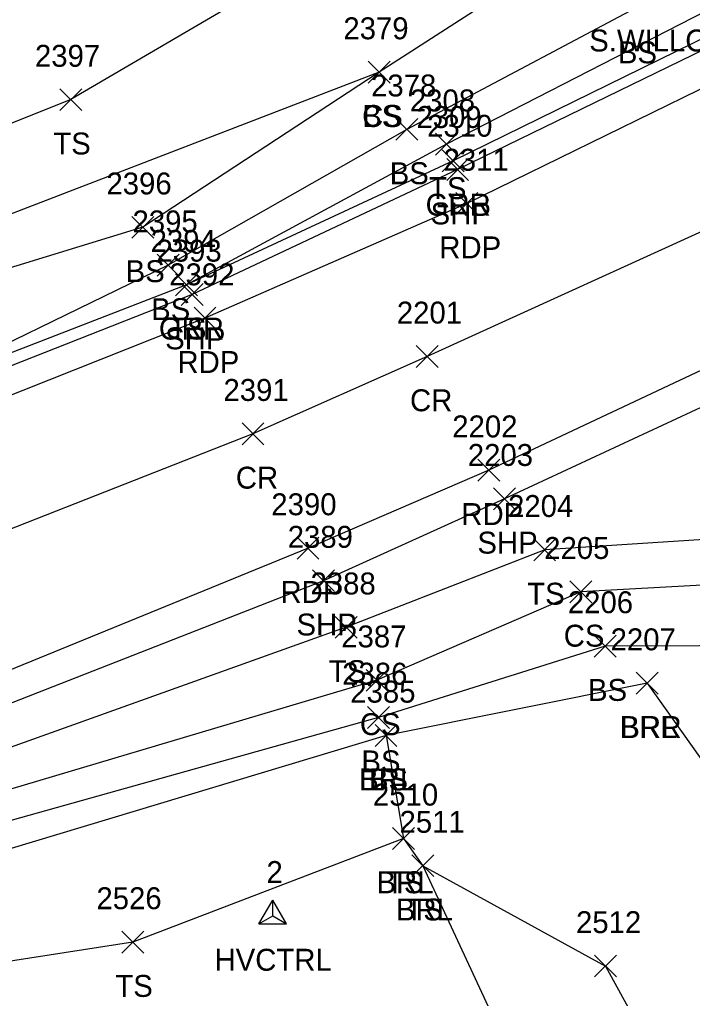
# Model space of a CAD drawing. Extents: x 1520648 to 1523413, y 732854 to 735518.
# Drawn here: x 1521920.9 to 1521982.3, y 733686.9 to 733776.2 of the extents above; entities that cross this region are included whole.
import ezdxf

# ---------------------------------------------------------------- set-up
doc = ezdxf.new("R2010")
doc.units = 0
for name, color, linetype in [('C_A', 7, 'Continuous'), ('C_I', 7, 'Continuous'), ('CPSM', 7, 'Continuous'), ('L_A', 7, 'Continuous'), ('L_C', 7, 'Continuous'), ('L_I', 7, 'Continuous'), ('L_TIC', 7, 'Continuous'), ('LABL', 7, 'Continuous'), ('LELB', 7, 'Continuous'), ('P_A', 7, 'Continuous'), ('P_I', 7, 'Continuous'), ('P_TIC', 7, 'Continuous'), ('PET', 7, 'Continuous'), ('PRC', 7, 'Continuous'), ('PSP', 7, 'Continuous'), ('R_A', 7, 'Continuous'), ('R_I', 7, 'Continuous'), ('R_TIC', 7, 'Continuous'), ('RGR', 7, 'Continuous')]:
    doc.layers.add(name, color=color, linetype=linetype)

msp = doc.modelspace()

# ---------------------------------------------------------------- linework, layer by layer
at = {"layer": 'CPSM'}
for p, q in [((1521942.773, 733693.671), (1521944.023, 733695.836)), ((1521942.773, 733693.671), (1521944.023, 733695.836)), ((1521942.773, 733693.671), (1521944.023, 733695.836)), ((1521942.773, 733693.671), (1521944.023, 733695.836)), ((1521942.773, 733693.671), (1521944.023, 733695.836)), ((1521942.773, 733693.671), (1521944.023, 733695.836)), ((1521942.773, 733693.671), (1521944.023, 733695.836)), ((1521942.773, 733693.671), (1521944.023, 733695.836)), ((1521945.273, 733693.671), (1521944.023, 733695.836)), ((1521944.023, 733694.392), (1521944.023, 733695.836)), ((1521945.273, 733693.671), (1521944.023, 733695.836)), ((1521944.023, 733694.392), (1521944.023, 733695.836)), ((1521945.273, 733693.671), (1521944.023, 733695.836)), ((1521944.023, 733694.392), (1521944.023, 733695.836)), ((1521945.273, 733693.671), (1521944.023, 733695.836)), ((1521944.023, 733694.392), (1521944.023, 733695.836)), ((1521945.273, 733693.671), (1521944.023, 733695.836)), ((1521944.023, 733694.392), (1521944.023, 733695.836)), ((1521945.273, 733693.671), (1521944.023, 733695.836)), ((1521944.023, 733694.392), (1521944.023, 733695.836)), ((1521945.273, 733693.671), (1521944.023, 733695.836)), ((1521944.023, 733694.392), (1521944.023, 733695.836)), ((1521945.273, 733693.671), (1521944.023, 733695.836)), ((1521944.023, 733694.392), (1521944.023, 733695.836)), ((1521942.773, 733693.671), (1521944.023, 733694.392)), ((1521942.773, 733693.671), (1521944.023, 733694.392)), ((1521942.773, 733693.671), (1521944.023, 733694.392)), ((1521942.773, 733693.671), (1521944.023, 733694.392)), ((1521942.773, 733693.671), (1521944.023, 733694.392)), ((1521942.773, 733693.671), (1521944.023, 733694.392)), ((1521942.773, 733693.671), (1521944.023, 733694.392)), ((1521942.773, 733693.671), (1521944.023, 733694.392)), ((1521944.023, 733694.392), (1521944.023, 733694.392)), ((1521944.023, 733694.392), (1521945.273, 733693.671)), ((1521944.023, 733694.392), (1521944.023, 733694.392)), ((1521944.023, 733694.392), (1521945.273, 733693.671)), ((1521944.023, 733694.392), (1521944.023, 733694.392)), ((1521944.023, 733694.392), (1521945.273, 733693.671)), ((1521944.023, 733694.392), (1521944.023, 733694.392)), ((1521944.023, 733694.392), (1521945.273, 733693.671)), ((1521944.023, 733694.392), (1521944.023, 733694.392)), ((1521944.023, 733694.392), (1521945.273, 733693.671)), ((1521944.023, 733694.392), (1521944.023, 733694.392)), ((1521944.023, 733694.392), (1521945.273, 733693.671)), ((1521944.023, 733694.392), (1521944.023, 733694.392)), ((1521944.023, 733694.392), (1521945.273, 733693.671)), ((1521944.023, 733694.392), (1521944.023, 733694.392)), ((1521944.023, 733694.392), (1521945.273, 733693.671)), ((1521942.773, 733693.671), (1521945.273, 733693.671)), ((1521942.773, 733693.671), (1521945.273, 733693.671)), ((1521942.773, 733693.671), (1521945.273, 733693.671)), ((1521942.773, 733693.671), (1521945.273, 733693.671)), ((1521942.773, 733693.671), (1521945.273, 733693.671)), ((1521942.773, 733693.671), (1521945.273, 733693.671)), ((1521942.773, 733693.671), (1521945.273, 733693.671)), ((1521942.773, 733693.671), (1521945.273, 733693.671))]:
    msp.add_line(p, q, dxfattribs=at)
at = {"layer": 'L_TIC'}
for points in [[(1521952.741, 733770.36), (1521954.741, 733772.36)], [(1521954.741, 733770.36), (1521952.741, 733772.36)], [(1521952.741, 733770.36), (1521954.741, 733772.36)], [(1521954.741, 733770.36), (1521952.741, 733772.36)], [(1521924.598, 733767.851), (1521926.598, 733769.851)], [(1521926.598, 733767.851), (1521924.598, 733769.851)], [(1521955.259, 733765.141), (1521957.259, 733767.141)], [(1521957.259, 733765.141), (1521955.259, 733767.141)], [(1521958.877, 733763.782), (1521960.877, 733765.782)], [(1521960.877, 733763.782), (1521958.877, 733765.782)], [(1521931.171, 733756.205), (1521933.171, 733758.205)], [(1521933.171, 733756.205), (1521931.171, 733758.205)], [(1521933.496, 733752.743), (1521935.496, 733754.743)], [(1521935.496, 733752.743), (1521933.496, 733754.743)], [(1521935.152, 733750.967), (1521937.152, 733752.967)], [(1521937.152, 733750.967), (1521935.152, 733752.967)], [(1521967.836, 733726.782), (1521969.836, 733728.782)], [(1521969.836, 733726.782), (1521967.836, 733728.782)], [(1521971.134, 733722.953), (1521973.134, 733724.953)], [(1521973.134, 733722.953), (1521971.134, 733724.953)], [(1521949.734, 733719.718), (1521951.734, 733721.718)], [(1521951.734, 733719.718), (1521949.734, 733721.718)], [(1521973.346, 733718.006), (1521975.346, 733720.006)], [(1521975.346, 733718.006), (1521973.346, 733720.006)], [(1521952.539, 733714.885), (1521954.539, 733716.885)], [(1521954.539, 733714.885), (1521952.539, 733716.885)], [(1521977.193, 733714.62), (1521979.193, 733716.62)], [(1521979.193, 733714.62), (1521977.193, 733716.62)], [(1521977.193, 733714.62), (1521979.193, 733716.62)], [(1521979.193, 733714.62), (1521977.193, 733716.62)], [(1521952.678, 733711.487), (1521954.678, 733713.487)], [(1521954.678, 733711.487), (1521952.678, 733713.487)], [(1521953.362, 733709.845), (1521955.362, 733711.845)], [(1521955.362, 733709.845), (1521953.362, 733711.845)], [(1521953.362, 733709.845), (1521955.362, 733711.845)], [(1521955.362, 733709.845), (1521953.362, 733711.845)], [(1521954.95, 733700.456), (1521956.95, 733702.456)], [(1521956.95, 733700.456), (1521954.95, 733702.456)], [(1521954.95, 733700.456), (1521956.95, 733702.456)], [(1521956.95, 733700.456), (1521954.95, 733702.456)], [(1521956.722, 733697.974), (1521958.722, 733699.974)], [(1521958.722, 733697.974), (1521956.722, 733699.974)], [(1521956.722, 733697.974), (1521958.722, 733699.974)], [(1521958.722, 733697.974), (1521956.722, 733699.974)], [(1521930.258, 733691.005), (1521932.258, 733693.005)], [(1521932.258, 733691.005), (1521930.258, 733693.005)], [(1521973.388, 733688.82), (1521975.388, 733690.82)], [(1521975.388, 733688.82), (1521973.388, 733690.82)]]:
    msp.add_lwpolyline(points, dxfattribs=at)
at = {"layer": 'LABL'}
for points in [[(1521978.193, 733715.62), (1521954.362, 733710.845), (1521955.95, 733701.456), (1521957.722, 733698.974), (1521966.054, 733681.007), (1521979.252, 733664.288), (1521978.744, 733653.004)], [(1521978.193, 733715.62), (1521987.07, 733703.125), (1521991.983, 733698.473), (1521999.135, 733685.223), (1521998.524, 733671.856), (1521978.744, 733653.004)]]:
    msp.add_lwpolyline(points, dxfattribs=at)
at = {"layer": 'LELB'}
for points in [[(1522083.308, 733923.237), (1522093.227, 733906.04), (1522109.507, 733889.846), (1522118.892, 733876.659), (1522124.085, 733871.16), (1522123.919, 733866.016), (1522119.878, 733860.124), (1522085.875, 733836.039), (1522047.289, 733811.543), (1522006.083, 733788.52), (1521959.877, 733764.782), (1521936.152, 733751.967)], [(1522074.665, 733922.228), (1522083.883, 733914.938), (1522085.489, 733904.133), (1522101.868, 733884.89), (1522107.237, 733877.569), (1522111.252, 733871.848), (1522110.649, 733869.41), (1522100.331, 733859.173), (1522100.269, 733856.435), (1522101.54, 733853.052), (1522099.302, 733851.621), (1522097.995, 733854.753), (1522097.241, 733854.62), (1522077.44, 733842.598), (1522038.26, 733821.738), (1522024.978, 733813.097), (1522007.394, 733798.444), (1521977.074, 733777.169), (1521956.259, 733766.141), (1521934.496, 733753.743), (1521909.848, 733741.767)], [(1521935.5, 733911.289), (1521950.9, 733894.839), (1521962.915, 733884.057), (1521979.81, 733864.62), (1521996.139, 733844.795), (1522019.287, 733822.837), (1522000.656, 733804.638), (1521971.808, 733783.007), (1521953.741, 733771.36), (1521896.074, 733749.167)], [(1521912.449, 733877.558), (1521921.717, 733856.63), (1521929.761, 733836.233), (1521943.688, 733808.595), (1521957.263, 733787.466), (1521947.51, 733781.711), (1521925.598, 733768.851), (1521901.287, 733759.134), (1521896.074, 733749.167), (1521874.343, 733737.13), (1521867.478, 733733.923)], [(1522137.237, 733813.36), (1522122.604, 733811.135), (1522114.406, 733809.375), (1522103.706, 733801.783), (1522081.649, 733783.392), (1522057.761, 733761.392), (1522025.51, 733740.121), (1522002.626, 733729.985), (1521968.836, 733727.782), (1521950.734, 733720.718), (1521906.643, 733704.941), (1521891.214, 733698.657), (1521885.295, 733693.938), (1521882.263, 733692.448), (1521879.875, 733686.549), (1521877.455, 733681.686), (1521874.746, 733671.189), (1521879.861, 733650.221), (1521887.887, 733627.143), (1521900.413, 733584.463), (1521909.701, 733557.243), (1521917.258, 733535.261)], [(1522120.862, 733803.477), (1522117.747, 733806.817), (1522113.051, 733804.251), (1522109.473, 733798.617), (1522083.975, 733778.274), (1522063.262, 733752.213), (1522037.469, 733737.801), (1522005.964, 733725.806), (1521972.134, 733723.953), (1521953.539, 733715.885), (1521907.93, 733702.346), (1521891.214, 733698.657)], [(1521953.741, 733771.36), (1521932.171, 733757.205), (1521906.082, 733749.21), (1521897.782, 733742.726), (1521876.406, 733735.089), (1521868.468, 733729.473), (1521856.113, 733726.295), (1521846.926, 733723.217), (1521807.832, 733711.49), (1521796.012, 733708.16), (1521783.934, 733704.847), (1521779.712, 733703.434)], [(1522023.756, 733721.952), (1522019.284, 733725.704), (1522008.74, 733719.105), (1521974.346, 733719.006), (1521953.678, 733712.487), (1521908.181, 733699.737), (1521890.734, 733695.159)], [(1521954.362, 733710.845), (1521908.425, 733697.009), (1521889.183, 733691.532), (1521888.015, 733691.887), (1521886.87, 733691.994), (1521886.465, 733692.996), (1521890.734, 733695.159)], [(1521955.95, 733701.456), (1521931.258, 733692.005), (1521914.217, 733689.344), (1521899.807, 733687.433), (1521885.45, 733683.539), (1521877.455, 733681.686)], [(1521957.722, 733698.974), (1521974.388, 733689.82), (1521985.192, 733670.143), (1521978.744, 733653.004), (1521963.108, 733617.364), (1521959.229, 733611.531), (1521945.534, 733595.31), (1521947.707, 733591.903), (1521931.806, 733568.241), (1521924.972, 733560.092), (1521929.188, 733550.052), (1521938.267, 733544.739)]]:
    msp.add_lwpolyline(points, dxfattribs=at)
at = {"layer": 'P_TIC'}
for points in [[(1521959.899, 733761.469), (1521961.899, 733763.469)], [(1521961.899, 733761.469), (1521959.899, 733763.469)], [(1521960.733, 733758.371), (1521962.733, 733760.371)], [(1521962.733, 733758.371), (1521960.733, 733760.371)], [(1521935.677, 733750.076), (1521937.677, 733752.076)], [(1521937.677, 733750.076), (1521935.677, 733752.076)], [(1521936.846, 733747.917), (1521938.846, 733749.917)], [(1521938.846, 733747.917), (1521936.846, 733749.917)], [(1521957.12, 733744.427), (1521959.12, 733746.427)], [(1521959.12, 733744.427), (1521957.12, 733746.427)], [(1521941.227, 733737.37), (1521943.227, 733739.37)], [(1521943.227, 733737.37), (1521941.227, 733739.37)], [(1521962.746, 733734.045), (1521964.746, 733736.045)], [(1521964.746, 733734.045), (1521962.746, 733736.045)], [(1521964.161, 733731.44), (1521966.161, 733733.44)], [(1521966.161, 733731.44), (1521964.161, 733733.44)], [(1521946.246, 733726.941), (1521948.246, 733728.941)], [(1521948.246, 733726.941), (1521946.246, 733728.941)], [(1521947.662, 733723.972), (1521949.662, 733725.972)], [(1521949.662, 733723.972), (1521947.662, 733725.972)]]:
    msp.add_lwpolyline(points, dxfattribs=at)
at = {"layer": 'PET'}
for points in [[(1522409.889, 734185.458), (1522384.803, 734151.862), (1522362.154, 734120.963), (1522340.089, 734090.379), (1522317.27, 734060.024), (1522297.221, 734033.868), (1522262.688, 733990.171), (1522247.435, 733972.23), (1522223.908, 733946.238), (1522192.475, 733913.956), (1522164.522, 733888.054), (1522124.702, 733855.724), (1522089.977, 733831.334), (1522050.332, 733806.095), (1522008.227, 733782.155), (1521961.733, 733759.371), (1521937.846, 733748.917), (1521892.742, 733731.021), (1521853.037, 733716.934), (1521810.117, 733704.128), (1521784.901, 733696.796), (1521738.039, 733684.332), (1521683.498, 733669.737)], [(1522293.194, 733992.175), (1522263.712, 733955.946), (1522232.455, 733921.589), (1522205.93, 733894.992), (1522171.676, 733864.451), (1522150.755, 733846.951), (1522111.89, 733818.73), (1522077.257, 733795.558), (1522046.35, 733777.345), (1522014.71, 733760.043), (1521992.386, 733748.515), (1521963.746, 733735.045), (1521947.246, 733727.941), (1521903.494, 733710.068), (1521845.394, 733690.649), (1521824.845, 733681.254), (1521803.807, 733674.865), (1521790.983, 733674.845), (1521764.049, 733667.923), (1521729.464, 733658.425), (1521691.158, 733648.143)]]:
    msp.add_lwpolyline(points, dxfattribs=at)
at = {"layer": 'PRC'}
msp.add_lwpolyline([(1522254.708, 733962.62), (1522224.204, 733928.998), (1522197.911, 733902.998), (1522164.255, 733873.016), (1522142.54, 733855.168), (1522104.412, 733827.43), (1522070.845, 733804.697), (1522039.569, 733786.252), (1522009.598, 733770.035), (1521986.99, 733758.562), (1521958.12, 733745.427), (1521942.227, 733738.37), (1521896.324, 733720.332), (1521857.71, 733706.322), (1521841.616, 733701.433), (1521812.172, 733692.842), (1521787.027, 733685.658), (1521768.249, 733680.623), (1521726.089, 733669.372), (1521688.171, 733658.559)], dxfattribs=at)
at = {"layer": 'PSP'}
for points in [[(1522407.438, 734186.957), (1522382.703, 734153.399), (1522359.979, 734122.447), (1522337.917, 734092.022), (1522315.008, 734061.409), (1522295.214, 734035.758), (1522260.619, 733991.788), (1522245.877, 733973.988), (1522222.051, 733948.064), (1522190.446, 733915.418), (1522160.989, 733888.489), (1522154.255, 733883.337), (1522127.344, 733861.553), (1522088.304, 733833.578), (1522048.983, 733808.783), (1522007.27, 733785.063), (1521960.899, 733762.469), (1521936.677, 733751.076), (1521891.961, 733733.483), (1521851.863, 733719.561), (1521809.017, 733706.622), (1521784.101, 733699.987), (1521736.058, 733688.523), (1521682.585, 733672.906)], [(1522408.205, 734139.279), (1522381.044, 734102.475), (1522353.021, 734064.874), (1522324.006, 734025.281), (1522296.174, 733989.549), (1522266.628, 733953.31), (1522235.292, 733918.787), (1522209.781, 733890.984), (1522201.901, 733884.12), (1522173.488, 733859.111), (1522154.026, 733843.415), (1522113.548, 733816.073), (1522079.344, 733793.188), (1522048.296, 733774.459), (1522016.588, 733757.423), (1521993.944, 733745.829), (1521965.161, 733732.44), (1521948.662, 733724.972), (1521904.277, 733707.61), (1521888.633, 733701.989), (1521847.287, 733686.723), (1521809.288, 733673.666)]]:
    msp.add_lwpolyline(points, dxfattribs=at)
at = {"layer": 'R_TIC'}
for points in [[(1521959.484, 733762.268), (1521961.484, 733764.268)], [(1521961.484, 733762.268), (1521959.484, 733764.268)], [(1521935.152, 733750.967), (1521937.152, 733752.967)], [(1521937.152, 733750.967), (1521935.152, 733752.967)]]:
    msp.add_lwpolyline(points, dxfattribs=at)
at = {"layer": 'RGR'}
msp.add_lwpolyline([(1522126.874, 733869.88), (1522125.456, 733863.286), (1522121.4, 733858.507), (1522087.424, 733834.282), (1522048.407, 733809.657), (1522007.43, 733786.325), (1521960.484, 733763.268), (1521936.152, 733751.967), (1521909.848, 733741.767), (1521879.817, 733730.479), (1521867.784, 733728.022), (1521851.141, 733720.486), (1521809.104, 733707.865), (1521796.227, 733704.909), (1521783.934, 733704.847)], dxfattribs=at)

# ---------------------------------------------------------------- texts
at = {"layer": 'C_A'}
msp.add_text('HVCTRL', height=2, dxfattribs=at).set_placement((1521938.716, 733689.392))
msp.add_text('HVCTRL', height=2, dxfattribs=at).set_placement((1521938.716, 733689.392))
msp.add_text('HVCTRL', height=2, dxfattribs=at).set_placement((1521938.716, 733689.392))
msp.add_text('HVCTRL', height=2, dxfattribs=at).set_placement((1521938.716, 733689.392))
msp.add_text('HVCTRL', height=2, dxfattribs=at).set_placement((1521938.716, 733689.392))
msp.add_text('HVCTRL', height=2, dxfattribs=at).set_placement((1521938.716, 733689.392))
msp.add_text('HVCTRL', height=2, dxfattribs=at).set_placement((1521938.716, 733689.392))
msp.add_text('HVCTRL', height=2, dxfattribs=at).set_placement((1521938.716, 733689.392))
at = {"layer": 'C_I'}
msp.add_text('2', height=2, dxfattribs=at).set_placement((1521943.456, 733697.392))
msp.add_text('2', height=2, dxfattribs=at).set_placement((1521943.456, 733697.392))
msp.add_text('2', height=2, dxfattribs=at).set_placement((1521943.456, 733697.392))
msp.add_text('2', height=2, dxfattribs=at).set_placement((1521943.456, 733697.392))
msp.add_text('2', height=2, dxfattribs=at).set_placement((1521943.456, 733697.392))
msp.add_text('2', height=2, dxfattribs=at).set_placement((1521943.456, 733697.392))
msp.add_text('2', height=2, dxfattribs=at).set_placement((1521943.456, 733697.392))
msp.add_text('2', height=2, dxfattribs=at).set_placement((1521943.456, 733697.392))
at = {"layer": 'L_A'}
for s, p in [('BS', (1521975.515, 733772.169)), ('CS', (1521952.182, 733766.36)), ('BS', (1521952.182, 733766.36)), ('TS', (1521924.008, 733763.851)), ('BS', (1521954.7, 733761.141)), ('TS', (1521958.287, 733759.782)), ('BS', (1521930.612, 733752.205)), ('BS', (1521932.937, 733748.743)), ('TS', (1521934.561, 733746.967)), ('TS', (1521967.245, 733722.782)), ('CS', (1521970.575, 733718.953)), ('TS', (1521949.144, 733715.718)), ('BS', (1521972.787, 733714.006)), ('CS', (1521951.98, 733710.885)), ('BRR', (1521975.681, 733710.62)), ('BRL', (1521975.737, 733710.62)), ('BS', (1521952.119, 733707.487)), ('BRL', (1521951.905, 733705.845)), ('BS', (1521952.803, 733705.845)), ('BRL', (1521953.493, 733696.456)), ('TS', (1521954.359, 733696.456)), ('BRL', (1521955.266, 733693.974)), ('TS', (1521956.132, 733693.974)), ('TS', (1521929.667, 733687.005))]:
    msp.add_text(s, height=2, dxfattribs=at).set_placement(p)
at = {"layer": 'L_C'}
msp.add_text('S.WILLOW', height=2, dxfattribs=at).set_placement((1521972.899, 733773.247))
at = {"layer": 'L_I'}
for s, p in [('2379', (1521950.473, 733774.36)), ('2379', (1521950.473, 733774.36)), ('2397', (1521922.338, 733771.851)), ('2378', (1521952.999, 733769.141)), ('2308', (1521956.539, 733767.782)), ('2396', (1521928.856, 733760.205)), ('2395', (1521931.237, 733756.743)), ('2394', (1521932.892, 733754.967)), ('2204', (1521965.497, 733730.782)), ('2205', (1521968.795, 733726.953)), ('2388', (1521947.474, 733723.718)), ('2206', (1521970.952, 733722.006)), ('2387', (1521950.279, 733718.885)), ('2207', (1521974.855, 733718.62)), ('2207', (1521974.855, 733718.62)), ('2386', (1521950.363, 733715.487)), ('2385', (1521951.102, 733713.845)), ('2385', (1521951.102, 733713.845)), ('2510', (1521953.17, 733704.456)), ('2510', (1521953.17, 733704.456)), ('2511', (1521955.596, 733701.974)), ('2511', (1521955.596, 733701.974)), ('2526', (1521927.943, 733695.005)), ('2512', (1521971.696, 733692.82))]:
    msp.add_text(s, height=2, dxfattribs=at).set_placement(p)
at = {"layer": 'P_A'}
for s, p in [('SHP', (1521958.434, 733757.469)), ('RDP', (1521959.222, 733754.371)), ('SHP', (1521934.213, 733746.076)), ('RDP', (1521935.334, 733743.917)), ('CR', (1521956.553, 733740.427)), ('CR', (1521940.66, 733733.37)), ('RDP', (1521961.234, 733730.045)), ('SHP', (1521962.697, 733727.44)), ('RDP', (1521944.734, 733722.941)), ('SHP', (1521946.198, 733719.972))]:
    msp.add_text(s, height=2, dxfattribs=at).set_placement(p)
at = {"layer": 'P_I'}
for s, p in [('2310', (1521958.119, 733765.469)), ('2311', (1521959.607, 733762.371)), ('2393', (1521933.418, 733754.076)), ('2392', (1521934.586, 733751.917)), ('2201', (1521955.348, 733748.427)), ('2391', (1521939.534, 733741.37)), ('2202', (1521960.407, 733738.045)), ('2203', (1521961.823, 733735.44)), ('2390', (1521943.899, 733730.941)), ('2389', (1521945.394, 733727.972))]:
    msp.add_text(s, height=2, dxfattribs=at).set_placement(p)
at = {"layer": 'R_A'}
for p in [(1521957.973, 733758.268), (1521933.64, 733746.967)]:
    msp.add_text('GRR', height=2, dxfattribs=at).set_placement(p)
at = {"layer": 'R_I'}
for s, p in [('2309', (1521957.138, 733766.268)), ('2394', (1521932.892, 733754.967))]:
    msp.add_text(s, height=2, dxfattribs=at).set_placement(p)

doc.saveas('drawing.dxf')
